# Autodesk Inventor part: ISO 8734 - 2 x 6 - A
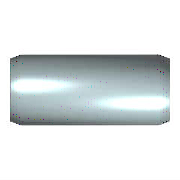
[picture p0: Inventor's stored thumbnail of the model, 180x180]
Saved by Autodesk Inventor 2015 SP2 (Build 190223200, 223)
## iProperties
IsCustomPart: 0
Created: 2012-02
Part Number: ISO 8734 - 2 x 6 - A
Material: Steel
Description: Parallel Pin
Document SubType Name: Modeling
Standard: ISO 8734
Designer: rYan
Standards Organization: DIN
Language: en-US
Size Designation: 2 x 6 - A
Categories: <MemberInstance><Categories><Category DisplayName="Fasteners" InternalName="e4da775c-781d-43d5-af7c-5136215cf5a6" Mnemonic="FSTN"><Category DisplayName="Pins" I
Density: 7.85 g/cm^3
Mass: 0.146401 g
Surface Area: 0.428007 cm^2
Volume: 0.0186498 cm^3
Appearance: Platte
Author: rYan
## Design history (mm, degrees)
sketch "Sketch"
  geometry: C1 r 1 at (0, 0); 1 further point
  constraints: 1 centre point, 1 coincident
  dimensions: "d1" = 2 diameter of C1 (= NND)
extrude "Body" new body sketch "Sketch" distance "d2" = 6 (= NLG); taper "d3" = 0 deg
chamfer "Chamfer1" distance "d4" = 0.35 (= PHH); stored, may be unused: angle "d5" = 15 deg (= FAWI), second distance "d11" = 0.35 (= PHH)
chamfer "Chamfer2" distance "d8" = 0.35 (= PHH); stored, may be unused: angle "d9" = 15 deg (= FAWI), second distance "d12" = 0.35 (= PHH)
body "Solid1"
other parameters: "NND" = 2 [user parameter; used in 1 equation term], "NLG" = 6 [user parameter; used in 1 equation term], "PHH" = 0.35 [user parameter; used in 5 equation terms], "FAWI" = 15 deg [user parameter; used in 2 equation terms], "d13" = 0, "d15" = 0, "d16" = 0, "PHH2" = 0.35 (= PHH) [user parameter], "FAWI2" = 15 deg [user parameter]
